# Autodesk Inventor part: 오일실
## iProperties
IsCustomPart: 0
Created: 2014-10
Part Number: 오일실
Material: 고무
Description: 오일-실
Document SubType Name: Modeling
Standard: KS B 2804
Designer: KYOUNG IL JANG
Standards Organization: KS
Language: ko-KR
Size Designation: D - 17 32 8
Categories: <MemberInstance><Categories><Category DisplayName="샤프트 부품" InternalName="7f7aeb1f-a693-4053-b835-cee3144e0d98" Mnemonic="SHFT"><Category DisplayName="실링" Intern
Density: 0.93 g/cm^3
Mass: 2.28027 g
Surface Area: 32.1224 cm^2
Volume: 2.45191 cm^3
Author: SeoGD™ [www.esajin.kr]
Revision Number: 1
